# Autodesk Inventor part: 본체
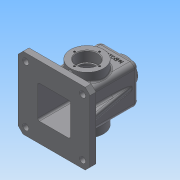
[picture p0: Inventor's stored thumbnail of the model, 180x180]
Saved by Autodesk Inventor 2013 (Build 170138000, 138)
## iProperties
Created: 2018-10
Part Number: 본체
Material: 일반
Document SubType Name: Modeling
Designer: Administrator
Density: 1 g/cm^3
Author: Administrator
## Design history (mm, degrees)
sketch "스케치1"
  geometry: L1 (-32.5, 32.5)-(32.5, 32.5); L2 (32.5, 32.5)-(32.5, -32.5); L3 (32.5, -32.5)-(-32.5, -32.5); L4 (-32.5, -32.5)-(-32.5, 32.5); L5 (-32.5, 32.5)-(32.5, -32.5); L6 (32.5, 32.5)-(-32.5, -32.5); 1 further point
  constraints: 12 end point, 2 midpoint, 2 parallel, 1 horizontal, 1 perpendicular
  dimensions: "d0" = 65 distance of L2.end L3.end; "d1" = 65 distance of L1.end L2.end
extrude "돌출1" new body sketch "스케치1" stored distance "d2" = 110; taper "d3" = 0 deg
sketch "스케치2"
  geometry: C1 r 27.5 at (32.5, -55); 1 further point
  constraints: 1 centre point, 1 coincident
  dimensions: "d4" = 55 diameter of C1
extrude "돌출2" join sketch "스케치2" distance "d5" = 15; taper "d6" = 0 deg
sketch "스케치3"
  geometry: C1 r 27.5 at (0, 0) reference; C2 r 17.5 at (0, 0)
  constraints: 1 centre point, 1 coincident
  dimensions: "d7" = 35 diameter of C2
extrude "돌출3" cut sketch "스케치3" distance "d8" = 17; taper "d9" = 0 deg
sketch "스케치4"
  geometry: C1 r 27.5 at (32.5, -55); 1 further point
  constraints: 1 centre point, 1 coincident
  dimensions: "d10" = 55 diameter of C1
extrude "돌출4" join sketch "스케치4" distance "d11" = 15; taper "d12" = 0 deg
sketch "스케치5"
  geometry: C1 r 27.5 at (0, 0) reference; C2 r 17.5 at (0, 0)
  constraints: 1 centre point, 1 coincident
  dimensions: "d13" = 35 diameter of C2
extrude "돌출5" cut sketch "스케치5" distance "d14" = 17; taper "d15" = 0 deg
feature "쉘1" dims "d16" = 5
hole "구멍1" diameter "d19" = 30; stored, may be unused: countersink angle "d23" = 90 deg, drill point angle "d25" = 118 deg; dims "d17" = 10, "d18" = 10, "d20" = 6, "d21" = 4, "d22" = 2, "d24" = 8
sketch "스케치6"
  geometry: L1 (32.5, 32.5)-(-32.5, 32.5) reference; L2 (-32.5, 32.5)-(-32.5, -32.5) reference; L3 (-32.5, -32.5)-(32.5, -32.5) reference; L4 (32.5, -32.5)-(32.5, 32.5) reference; L5 (-60, 60)-(60, 60); L6 (60, 60)-(60, -60); L7 (60, -60)-(-60, -60); L8 (-60, -60)-(-60, 60); L9 (-60, 60)-(60, -60); L10 (60, 60)-(-60, -60); 1 further point
  constraints: 12 end point, 2 midpoint, 2 parallel, 1 horizontal, 1 perpendicular
  dimensions: "d26" = 120 distance of L6.end L7.end; "d27" = 120 distance of L5.end L6.end
extrude "돌출6" join sketch "스케치6" distance "d28" = 10; taper "d29" = 0 deg
fillet "모깎기1" dims "d30" = 8
fillet "모깎기2" dims "d31" = 8
fillet "모깎기3" dims "d32" = 3
fillet "모깎기4" dims "d33" = 3
chamfer "모따기1" distance "d34" = 8; stored, may be unused: second distance "d35" = 2, angle "d36" = 45 deg
node "작업 평면1"
sketch "스케치7"
  geometry: C1 r 20 at (0, 0); 1 further point
  constraints: 1 centre point, 1 coincident
  dimensions: "d38" = 40 diameter of C1
extrude "돌출7" join sketch "스케치7" distance "d39" = 10; taper "d40" = 7 deg
hole "구멍2" diameter "d43" = 22.835; stored, may be unused: countersink angle "d47" = 90 deg, drill point angle "d49" = 118 deg; dims "d41" = 10, "d42" = 10, "d44" = 50, "d45" = 4, "d46" = 2, "d48" = 8
sketch "스케치8"
  geometry: C1 r 5 at (47.5, 47.5); 1 further point
  constraints: 1 centre point
  dimensions: "d50" = 10 diameter of C1; "d51" = 47.5 horizontal distance of C1.centre point (0, 0); "d52" = 47.5 horizontal distance of C1.centre point (0, 0)
extrude "돌출8" cut sketch "스케치8" stored distance "d53" = 10; taper "d54" = 0 deg
sketch "스케치9"
  geometry: L1 (42.5, -45)-(52.5, -45) reference; L2 (32.5, 47)-(32.5, -45) reference; L3 (52, -45)-(-52, -45) reference; L4 (48, -45)-(32.5, 42.905); L5 (60, -45)-(60, -55) reference; 1 further point
  constraints: 2 end point, 2 point on line
  dimensions: "d55" = 12 distance from line of L5 L4.start; "d56" = 10 deg angle of L5 L4
feature "리브1" sketch "스케치9" dims "d57" = 1, "d58" = 10, "d59" = 0, "d60" = 0, "d61" = 1, "d62" = 1
sketch "스케치11"
  geometry: L1 (27.5, 47.5)-(-27.5, 47.5) reference; L2 (12.49, 32.5)-(12.49, 32.5) reference; L3 (-12.49, 32.5)-(-12.49, 32.5) reference; L4 (-27.5, 32.5)-(-27.5, 47.5) reference; L5 (-55, -52)-(-55, 52) reference; L6 (-45, 52)-(-55, 52) reference; L7 (-45, -52)-(-45, 52) reference; L8 (-55, -52)-(-45, -52) reference; L9 (-45, 42.5)-(-27.5, 42.5); L10 (-45, 32.5)-(-12.49, 32.5) reference; L11 (47, 27.5)-(-55, 27.5) reference; 1 further point
  constraints: 2 end point, 2 horizontal alignment, 2 point on line, 1 parallel
  dimensions: "d65" = 15 distance between parallel lines of L11 L9
feature "리브2" sketch "스케치11" dims "d66" = 1, "d67" = 6, "d68" = 0, "d69" = 0, "d70" = 1, "d71" = 1
fillet "모깎기5" dims "d72" = 3
fillet "모깎기6" dims "d73" = 3
fillet "모깎기7" dims "d74" = 3
fillet "모깎기8" dims "d75" = 3
fillet "모깎기9" dims "d76" = 3
sketch "스케치12"
  geometry: L1 (0, 0)-(0, 21); C1 r 27.5 at (0, 0) reference; 1 further point
  constraints: 2 end point, 1 coincident, 1 vertical
  dimensions: "d77" = 21 distance of L1.start L1.end
hole "구멍3" sketch "스케치12" at (0, 21) diameter "d78" = 3.242; stored, may be unused: countersink angle "d82" = 90 deg, drill point angle "d84" = 118 deg; dims "d79" = 8, "d80" = 4, "d81" = 2, "d83" = 10
fillet "모깎기10" dims "d88" = 0.3
chamfer "모따기2" distance "d89" = 1; stored, may be unused: second distance "d90" = 2, angle "d91" = 45 deg
sketch "스케치13"
  geometry: L1 (4.5, 18)-(44.5, 18) reference; A1 r 30.5 centre (24.5, -47) between (49, -28.834) and (0, -28.834) reference; 1 further point
  constraints: 1 vertical alignment, 1 other
  dimensions: "d92" = 26 distance from line of L1 point (24.5, -8)
feature "엠보싱1" sketch "스케치13" dims "d93" = 0.5, "d94" = 0
chamfer "모따기3" distance "d95" = 1; stored, may be unused: second distance "d96" = 2, angle "d97" = 45 deg
fillet "모깎기11" dims "d98" = 3
fillet "모깎기12" dims "d99" = 1
sketch "스케치14"
  geometry: L1 (-24.5, 27.5)-(24.5, 27.5) reference; L2 (27.5, 24.5)-(27.5, -24.5) reference; L3 (24.5, -27.5)-(-24.5, -27.5) reference; L4 (-27.5, -24.5)-(-27.5, 24.5) reference; A1 r 3 centre (24.5, 24.5) between (27.5, 24.5) and (24.5, 27.5) reference; A2 r 3 centre (24.5, -24.5) between (24.5, -27.5) and (27.5, -24.5) reference; A3 r 3 centre (-24.5, -24.5) between (-27.5, -24.5) and (-24.5, -27.5) reference; A4 r 3 centre (-24.5, 24.5) between (-24.5, 27.5) and (-27.5, 24.5) reference; 1 further point
extrude "돌출9" cut sketch "스케치14" distance "d100" = 88.5; taper "d101" = 0 deg
node "솔리드1"
mirror "대칭1"
mirror "대칭2"
mirror "대칭3"
mirror "대칭4"
pattern_circular "원형 패턴1" dims angle "d86" = 360 deg
mirror "대칭5"
node "투영된 루프1"
node "투영된 루프2"
other parameters: "d37" = 65
